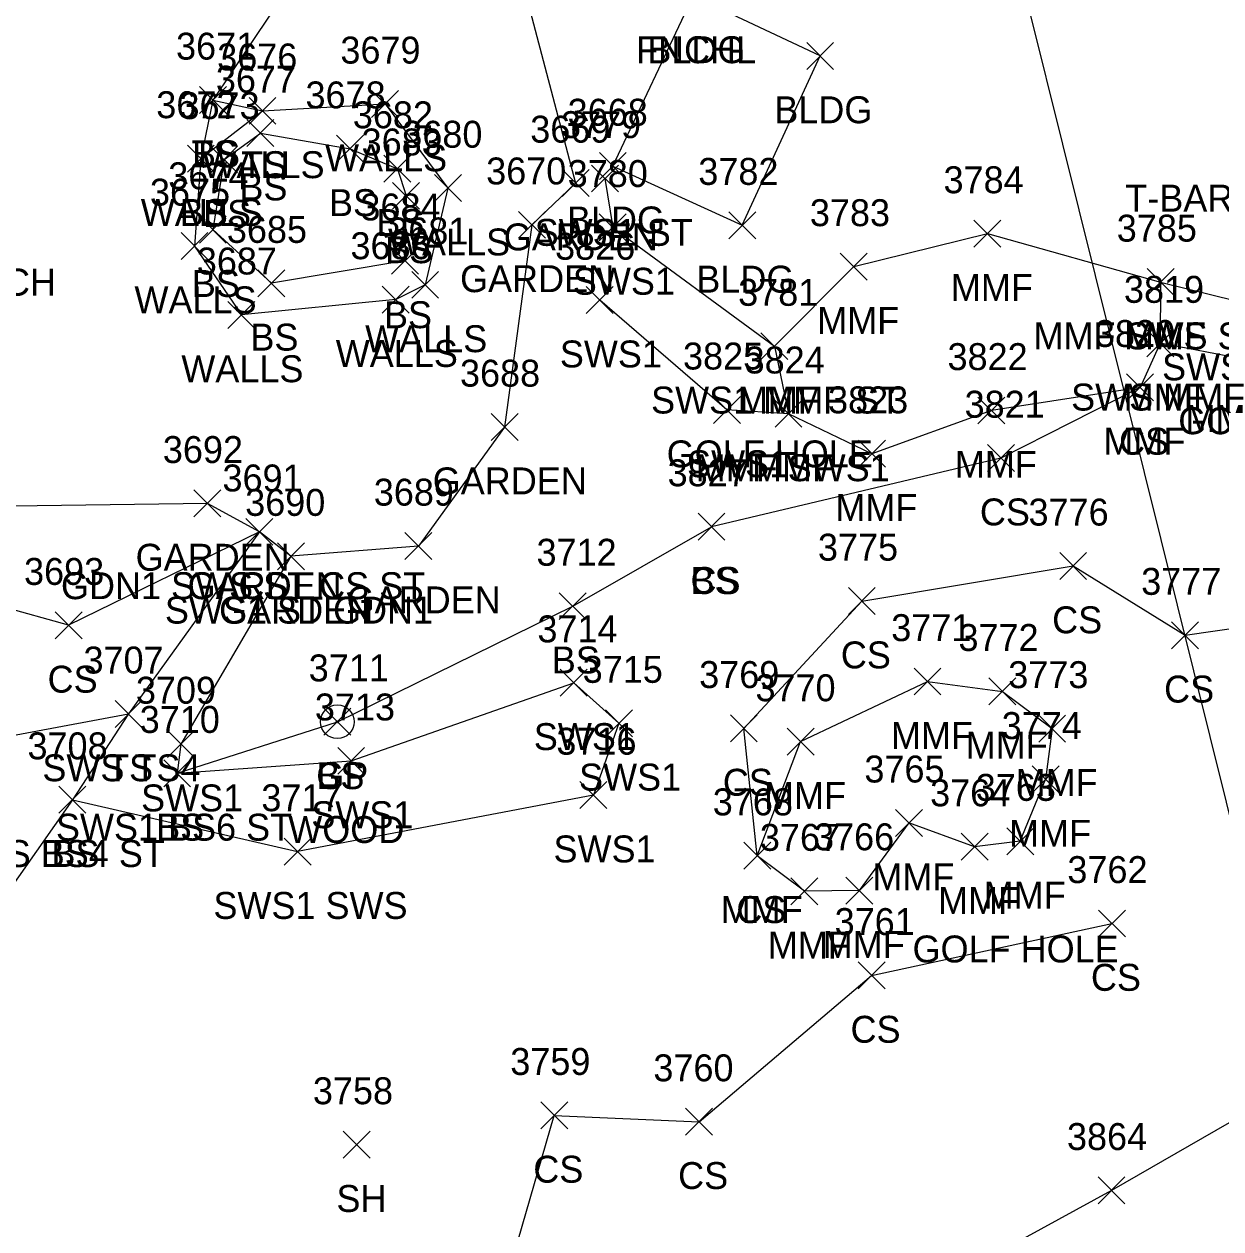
# Model space of a CAD drawing. Extents: x 49137 to 50946, y 9590 to 10709.
# Drawn here: x 49965.3 to 50054.1, y 10323.2 to 10412.7 of the extents above; entities that cross this region are included whole.
import ezdxf

# ---------------------------------------------------------------- set-up
doc = ezdxf.new("R2010")
doc.units = 0
for name, color, linetype in [('DCP', 7, 'Continuous'), ('L_A', 7, 'Continuous'), ('L_C', 7, 'Continuous'), ('L_I', 7, 'Continuous'), ('L_TIC', 7, 'Continuous'), ('LAPB', 7, 'Continuous'), ('LBC', 7, 'Continuous'), ('LDEFAULT', 7, 'Continuous'), ('LELB', 7, 'Continuous'), ('LWS', 7, 'Continuous'), ('R_A', 7, 'Continuous'), ('R_C', 7, 'Continuous'), ('R_I', 7, 'Continuous'), ('R_TIC', 7, 'Continuous'), ('RGP', 7, 'Continuous'), ('RSW', 7, 'Continuous')]:
    doc.layers.add(name, color=color, linetype=linetype)

msp = doc.modelspace()

# ---------------------------------------------------------------- linework, layer by layer
at = {"layer": 'DCP'}
msp.add_lwpolyline([(50149.417, 9973.365), (49988.848, 10619.092)], dxfattribs=at)
at = {"layer": 'L_TIC'}
for points in [[(50023.366, 10409.355), (50025.366, 10411.355)], [(50025.366, 10409.355), (50023.366, 10411.355)], [(49978.28, 10406.08), (49980.28, 10408.08)], [(49980.28, 10406.08), (49978.28, 10408.08)], [(49978.28, 10406.08), (49980.28, 10408.08)], [(49980.28, 10406.08), (49978.28, 10408.08)], [(49991.059, 10405.785), (49993.059, 10407.785)], [(49993.059, 10405.785), (49991.059, 10407.785)], [(49981.959, 10405.277), (49983.959, 10407.277)], [(49983.959, 10405.277), (49981.959, 10407.277)], [(49981.959, 10405.277), (49983.959, 10407.277)], [(49983.959, 10405.277), (49981.959, 10407.277)], [(49981.804, 10403.626), (49983.804, 10405.626)], [(49983.804, 10403.626), (49981.804, 10405.626)], [(49988.459, 10402.458), (49990.459, 10404.458)], [(49990.459, 10402.458), (49988.459, 10404.458)], [(49977.379, 10401.73), (49979.379, 10403.73)], [(49979.379, 10401.73), (49977.379, 10403.73)], [(49977.379, 10401.73), (49979.379, 10403.73)], [(49979.379, 10401.73), (49977.379, 10403.73)], [(49977.379, 10401.73), (49979.379, 10403.73)], [(49979.379, 10401.73), (49977.379, 10403.73)], [(49979.103, 10401.661), (49981.103, 10403.661)], [(49981.103, 10401.661), (49979.103, 10403.661)], [(49979.103, 10401.661), (49981.103, 10403.661)], [(49981.103, 10401.661), (49979.103, 10403.661)], [(50007.97, 10401.171), (50009.97, 10403.171)], [(50009.97, 10401.171), (50007.97, 10403.171)], [(50007.97, 10401.171), (50009.97, 10403.171)], [(50009.97, 10401.171), (50007.97, 10403.171)], [(49991.973, 10400.98), (49993.973, 10402.98)], [(49993.973, 10400.98), (49991.973, 10402.98)], [(49995.732, 10399.538), (49997.732, 10401.538)], [(49997.732, 10399.538), (49995.732, 10401.538)], [(50005.203, 10399.914), (50007.203, 10401.914)], [(50007.203, 10399.914), (50005.203, 10401.914)], [(49992.624, 10398.963), (49994.624, 10400.963)], [(49994.624, 10398.963), (49992.624, 10400.963)], [(50001.96, 10396.811), (50003.96, 10398.811)], [(50003.96, 10396.811), (50001.96, 10398.811)], [(50017.577, 10396.777), (50019.577, 10398.777)], [(50019.577, 10396.777), (50017.577, 10398.777)], [(49978.27, 10396.452), (49980.27, 10398.452)], [(49980.27, 10396.452), (49978.27, 10398.452)], [(50035.786, 10396.157), (50037.786, 10398.157)], [(50037.786, 10396.157), (50035.786, 10398.157)], [(49976.91, 10395.237), (49978.91, 10397.237)], [(49978.91, 10395.237), (49976.91, 10397.237)], [(49992.535, 10394.136), (49994.535, 10396.136)], [(49994.535, 10394.136), (49992.535, 10396.136)], [(50025.86, 10393.712), (50027.86, 10395.712)], [(50027.86, 10393.712), (50025.86, 10395.712)], [(49982.62, 10392.47), (49984.62, 10394.47)], [(49984.62, 10392.47), (49982.62, 10394.47)], [(49982.62, 10392.47), (49984.62, 10394.47)], [(49984.62, 10392.47), (49982.62, 10394.47)], [(49994.036, 10392.354), (49996.036, 10394.354)], [(49996.036, 10392.354), (49994.036, 10394.354)], [(50048.646, 10392.563), (50050.646, 10394.563)], [(50050.646, 10392.563), (50048.646, 10394.563)], [(49991.854, 10391.259), (49993.854, 10393.259)], [(49993.854, 10391.259), (49991.854, 10393.259)], [(49980.389, 10390.123), (49982.389, 10392.123)], [(49982.389, 10390.123), (49980.389, 10392.123)], [(49980.389, 10390.123), (49982.389, 10392.123)], [(49982.389, 10390.123), (49980.389, 10392.123)], [(50019.968, 10387.798), (50021.968, 10389.798)], [(50021.968, 10387.798), (50019.968, 10389.798)], [(50048.621, 10388.018), (50050.621, 10390.018)], [(50050.621, 10388.018), (50048.621, 10390.018)], [(50047.112, 10384.74), (50049.112, 10386.74)], [(50049.112, 10384.74), (50047.112, 10386.74)], [(50047.112, 10384.74), (50049.112, 10386.74)], [(50049.112, 10384.74), (50047.112, 10386.74)], [(50021.015, 10382.772), (50023.015, 10384.772)], [(50023.015, 10382.772), (50021.015, 10384.772)], [(50036.08, 10383.022), (50038.08, 10385.022)], [(50038.08, 10383.022), (50036.08, 10385.022)], [(49999.93, 10381.794), (50001.93, 10383.794)], [(50001.93, 10381.794), (49999.93, 10383.794)], [(50027.208, 10379.812), (50029.208, 10381.812)], [(50029.208, 10379.812), (50027.208, 10381.812)], [(50036.783, 10379.488), (50038.783, 10381.488)], [(50038.783, 10379.488), (50036.783, 10381.488)], [(49977.869, 10376.122), (49979.869, 10378.122)], [(49979.869, 10376.122), (49977.869, 10378.122)], [(50015.297, 10374.395), (50017.297, 10376.395)], [(50017.297, 10374.395), (50015.297, 10376.395)], [(50015.297, 10374.395), (50017.297, 10376.395)], [(50017.297, 10374.395), (50015.297, 10376.395)], [(49981.728, 10374.011), (49983.728, 10376.011)], [(49983.728, 10374.011), (49981.728, 10376.011)], [(49981.728, 10374.011), (49983.728, 10376.011)], [(49983.728, 10374.011), (49981.728, 10376.011)], [(49993.536, 10372.957), (49995.536, 10374.957)], [(49995.536, 10372.957), (49993.536, 10374.957)], [(49984.067, 10372.198), (49986.067, 10374.198)], [(49986.067, 10372.198), (49984.067, 10374.198)], [(50042.148, 10371.476), (50044.148, 10373.476)], [(50044.148, 10371.476), (50042.148, 10373.476)], [(50004.996, 10368.493), (50006.996, 10370.493)], [(50006.996, 10368.493), (50004.996, 10370.493)], [(50026.458, 10368.871), (50028.458, 10370.871)], [(50028.458, 10368.871), (50026.458, 10370.871)], [(49967.562, 10367.069), (49969.562, 10369.069)], [(49969.562, 10367.069), (49967.562, 10369.069)], [(50050.46, 10366.333), (50052.46, 10368.333)], [(50052.46, 10366.333), (50050.46, 10368.333)], [(50031.333, 10362.895), (50033.333, 10364.895)], [(50033.333, 10362.895), (50031.333, 10364.895)], [(50036.893, 10362.163), (50038.893, 10364.163)], [(50038.893, 10362.163), (50036.893, 10364.163)], [(49972.009, 10360.489), (49974.009, 10362.489)], [(49974.009, 10360.489), (49972.009, 10362.489)], [(49987.517, 10359.904), (49989.517, 10361.904)], [(49989.517, 10359.904), (49987.517, 10361.904)], [(50017.697, 10359.413), (50019.697, 10361.413)], [(50019.697, 10359.413), (50017.697, 10361.413)], [(50040.591, 10359.403), (50042.591, 10361.403)], [(50042.591, 10359.403), (50040.591, 10361.403)], [(50021.908, 10358.429), (50023.908, 10360.429)], [(50023.908, 10358.429), (50021.908, 10360.429)], [(49975.622, 10356.077), (49977.622, 10358.077)], [(49977.622, 10356.077), (49975.622, 10358.077)], [(50040.104, 10355.622), (50042.104, 10357.622)], [(50042.104, 10355.622), (50040.104, 10357.622)], [(50040.104, 10355.622), (50042.104, 10357.622)], [(50042.104, 10355.622), (50040.104, 10357.622)], [(49967.847, 10354.118), (49969.847, 10356.118)], [(49969.847, 10354.118), (49967.847, 10356.118)], [(50029.956, 10352.395), (50031.956, 10354.395)], [(50031.956, 10352.395), (50029.956, 10354.395)], [(50034.836, 10350.628), (50036.836, 10352.628)], [(50036.836, 10350.628), (50034.836, 10352.628)], [(50038.223, 10351.032), (50040.223, 10353.032)], [(50040.223, 10351.032), (50038.223, 10353.032)], [(50038.223, 10351.032), (50040.223, 10353.032)], [(50040.223, 10351.032), (50038.223, 10353.032)], [(50018.697, 10349.956), (50020.697, 10351.956)], [(50020.697, 10349.956), (50018.697, 10351.956)], [(50018.697, 10349.956), (50020.697, 10351.956)], [(50020.697, 10349.956), (50018.697, 10351.956)], [(50022.196, 10347.321), (50024.196, 10349.321)], [(50024.196, 10347.321), (50022.196, 10349.321)], [(50026.271, 10347.363), (50028.271, 10349.363)], [(50028.271, 10347.363), (50026.271, 10349.363)], [(50045.027, 10344.926), (50047.027, 10346.926)], [(50047.027, 10344.926), (50045.027, 10346.926)], [(50027.179, 10341.067), (50029.179, 10343.067)], [(50029.179, 10341.067), (50027.179, 10343.067)], [(50003.625, 10330.677), (50005.625, 10332.677)], [(50005.625, 10330.677), (50003.625, 10332.677)], [(50014.376, 10330.206), (50016.376, 10332.206)], [(50016.376, 10330.206), (50014.376, 10332.206)], [(49988.961, 10328.503), (49990.961, 10330.503)], [(49990.961, 10328.503), (49988.961, 10330.503)], [(50044.996, 10325.102), (50046.996, 10327.102)], [(50046.996, 10325.102), (50044.996, 10327.102)]]:
    msp.add_lwpolyline(points, dxfattribs=at)
at = {"layer": 'LAPB'}
msp.add_lwpolyline([(49952.358, 10434.146), (49968.592, 10432.435), (49977.813, 10428.307), (49990.651, 10424.08), (50000.797, 10421.39), (50006.203, 10400.914), (50002.96, 10397.811), (50000.93, 10382.794), (49994.536, 10373.957), (49985.067, 10373.198), (49982.728, 10375.011), (49978.869, 10377.122), (49955.361, 10376.803), (49948.643, 10373.628)], dxfattribs=at)
at = {"layer": 'LBC'}
for points in [[(50008.97, 10402.171), (50018.577, 10397.777), (50024.366, 10410.355), (50014.946, 10414.815)], [(50008.97, 10402.171), (50014.946, 10414.815)]]:
    msp.add_lwpolyline(points, dxfattribs=at)
at = {"layer": 'LDEFAULT'}
for points in [[(50020.968, 10388.798), (50026.86, 10394.712), (50036.786, 10397.157), (50049.646, 10393.563), (50049.621, 10389.018), (50048.112, 10385.74), (50037.08, 10384.022), (50028.208, 10380.812), (50022.015, 10383.772)], [(50039.223, 10352.032), (50035.836, 10351.628), (50030.956, 10353.395), (50027.271, 10348.363), (50023.196, 10348.321), (50019.697, 10350.956), (50022.908, 10359.429), (50032.333, 10363.895), (50037.893, 10363.163), (50041.591, 10360.403), (50041.104, 10356.622)], [(50039.223, 10352.032), (50041.104, 10356.622)]]:
    msp.add_lwpolyline(points, dxfattribs=at)
at = {"layer": 'LELB'}
for points in [[(49990.651, 10424.08), (49979.28, 10407.08), (49978.379, 10402.73)], [(49979.28, 10407.08), (49982.959, 10406.277)], [(49980.103, 10402.661), (49982.804, 10404.626), (49989.459, 10403.458), (49992.973, 10401.98), (49993.624, 10399.963), (49993.535, 10395.136), (49983.62, 10393.47)], [(49980.103, 10402.661), (49979.27, 10397.452), (49983.62, 10393.47)], [(50048.112, 10385.74), (50037.783, 10380.488), (50016.297, 10375.395)], [(50019.697, 10350.956), (50018.697, 10360.413), (50027.458, 10369.871), (50043.148, 10372.476), (50051.46, 10367.333), (50060.907, 10368.69), (50071.028, 10377.965)], [(49982.728, 10375.011), (49968.562, 10368.069), (49948.643, 10373.628)], [(49976.622, 10357.077), (49988.517, 10360.904), (50005.996, 10369.493), (50016.297, 10375.395)], [(49926.539, 10346.599), (49938.324, 10352.703), (49953.777, 10357.903), (49973.009, 10361.489)], [(49968.847, 10355.118), (49955.47, 10336.036), (49948.518, 10322.541), (49945.706, 10295.254), (49955.228, 10276.315), (49969.259, 10262.531), (49976.787, 10237.905)], [(49969.259, 10262.531), (49980.294, 10281.069), (49996.572, 10303.842), (50004.625, 10331.677), (50015.376, 10331.206), (50028.179, 10342.067), (50046.027, 10345.926)], [(50066.256, 10337.749), (50045.996, 10326.102), (50031.571, 10318.205), (50024.186, 10311.328), (50008.365, 10283.785), (50010.84, 10269.9), (50019.682, 10261.76), (50041.865, 10254.082), (50068.201, 10243.093)]]:
    msp.add_lwpolyline(points, dxfattribs=at)
at = {"layer": 'LWS'}
for points in [[(49978.379, 10402.73), (49982.959, 10406.277), (49992.059, 10406.785), (49996.732, 10400.538), (49995.036, 10393.354), (49992.854, 10392.259), (49981.389, 10391.123)], [(49978.379, 10402.73), (49977.91, 10396.237), (49981.389, 10391.123)]]:
    msp.add_lwpolyline(points, dxfattribs=at)
at = {"layer": 'R_TIC'}
for points in [[(50007.387, 10400.251), (50009.387, 10402.251)], [(50009.387, 10400.251), (50007.387, 10402.251)], [(50007.963, 10396.62), (50009.963, 10398.62)], [(50009.963, 10396.62), (50007.963, 10398.62)], [(50048.646, 10392.563), (50050.646, 10394.563)], [(50050.646, 10392.563), (50048.646, 10394.563)], [(50006.998, 10391.22), (50008.998, 10393.22)], [(50008.998, 10391.22), (50006.998, 10393.22)], [(50019.968, 10387.798), (50021.968, 10389.798)], [(50021.968, 10387.798), (50019.968, 10389.798)], [(50048.621, 10388.018), (50050.621, 10390.018)], [(50050.621, 10388.018), (50048.621, 10390.018)], [(50016.443, 10383.066), (50018.443, 10385.066)], [(50018.443, 10383.066), (50016.443, 10385.066)], [(50021.015, 10382.772), (50023.015, 10384.772)], [(50023.015, 10382.772), (50021.015, 10384.772)], [(49981.728, 10374.011), (49983.728, 10376.011)], [(49983.728, 10374.011), (49981.728, 10376.011)], [(49984.067, 10372.198), (49986.067, 10374.198)], [(49986.067, 10372.198), (49984.067, 10374.198)], [(50005.065, 10362.803), (50007.065, 10364.803)], [(50007.065, 10362.803), (50005.065, 10364.803)], [(49972.009, 10360.489), (49974.009, 10362.489)], [(49974.009, 10360.489), (49972.009, 10362.489)], [(50008.426, 10359.798), (50010.426, 10361.798)], [(50010.426, 10359.798), (50008.426, 10361.798)], [(49975.906, 10358.249), (49977.906, 10360.249)], [(49977.906, 10358.249), (49975.906, 10360.249)], [(49988.541, 10357.004), (49990.541, 10359.004)], [(49990.541, 10357.004), (49988.541, 10359.004)], [(49975.622, 10356.077), (49977.622, 10358.077)], [(49977.622, 10356.077), (49975.622, 10358.077)], [(49967.847, 10354.118), (49969.847, 10356.118)], [(49969.847, 10354.118), (49967.847, 10356.118)], [(50006.526, 10354.461), (50008.526, 10356.461)], [(50008.526, 10354.461), (50006.526, 10356.461)], [(49984.568, 10350.265), (49986.568, 10352.265)], [(49986.568, 10350.265), (49984.568, 10352.265)], [(49984.568, 10350.265), (49986.568, 10352.265)], [(49986.568, 10350.265), (49984.568, 10352.265)]]:
    msp.add_lwpolyline(points, dxfattribs=at)
at = {"layer": 'RGP'}
msp.add_line((49988.517, 10360.904), (49988.517, 10360.904), dxfattribs=at)
for radius in [1.25, 0.0833]:
    msp.add_circle((49988.517, 10360.904), radius, dxfattribs=at)
at = {"layer": 'RSW'}
for points in [[(50008.387, 10401.251), (50008.963, 10397.62), (50020.968, 10388.798), (50022.015, 10383.772), (50017.443, 10384.066), (50007.998, 10392.22)], [(50049.646, 10393.563), (50058.954, 10391.261), (50057.822, 10387.436), (50049.621, 10389.018)], [(49982.728, 10375.011), (49973.009, 10361.489), (49968.847, 10355.118), (49985.568, 10351.265)], [(49985.067, 10373.198), (49976.906, 10359.249), (49976.622, 10357.077), (49989.541, 10358.004), (50006.065, 10363.803), (50009.426, 10360.798), (50007.526, 10355.461), (49985.568, 10351.265)]]:
    msp.add_lwpolyline(points, dxfattribs=at)

# ---------------------------------------------------------------- texts
at = {"layer": 'L_A'}
for s, p in [('FNCHL', (50010.694, 10409.815)), ('BLDG', (50011.536, 10409.815)), ('BLDG', (50011.536, 10409.815)), ('BLDG', (50020.957, 10405.355)), ('TS', (49977.689, 10402.08)), ('BS', (49977.721, 10402.08)), ('WALLS', (49978.502, 10401.277)), ('TS', (49981.368, 10401.277)), ('WALLS', (49987.602, 10401.785)), ('BS', (49981.245, 10399.626)), ('BS', (49987.9, 10398.458)), ('WALLS', (49973.922, 10397.73)), ('WALLS', (49973.922, 10397.73)), ('BS', (49976.82, 10397.73)), ('BS', (49978.544, 10397.661)), ('BS', (49978.544, 10397.661)), ('BS', (49991.413, 10396.98)), ('BLDG', (50005.56, 10397.171)), ('BLDG', (50005.56, 10397.171)), ('GARDEN', (50000.872, 10395.914)), ('BS', (49992.065, 10394.963)), ('WALLS', (49992.275, 10395.538)), ('BS', (49977.711, 10392.452)), ('GARDEN', (49997.629, 10392.811)), ('BLDG', (50015.168, 10392.777)), ('MMF', (50034.07, 10392.157)), ('WALLS', (49973.453, 10391.237)), ('BS', (49991.976, 10390.136)), ('MMF', (50024.144, 10389.712)), ('BS', (49982.061, 10388.47)), ('BS', (49982.061, 10388.47)), ('WALLS', (49990.58, 10388.354)), ('MMF', (50046.93, 10388.563)), ('WALLS', (49988.398, 10387.259)), ('WALLS', (49976.933, 10386.123)), ('WALLS', (49976.933, 10386.123)), ('MMF', (50018.251, 10383.798)), ('MMF', (50046.905, 10384.018)), ('MMF', (50045.395, 10380.74)), ('CS', (50046.553, 10380.74)), ('MMF', (50034.364, 10379.022)), ('MMF', (50019.299, 10378.772)), ('GARDEN', (49995.599, 10377.794)), ('MMF', (50025.492, 10375.812)), ('CS', (50036.224, 10375.488)), ('GARDEN', (49973.538, 10372.122)), ('GARDEN', (49977.397, 10370.011)), ('CS', (49981.169, 10370.011)), ('CS', (50014.738, 10370.395)), ('BS', (50014.738, 10370.395)), ('GARDEN', (49989.206, 10368.957)), ('GARDEN', (49979.737, 10368.198)), ('CS', (50041.589, 10367.476)), ('BS', (50004.437, 10364.493)), ('CS', (50025.899, 10364.871)), ('CS', (49967.003, 10363.069)), ('CS', (50049.901, 10362.333)), ('MMF', (50029.617, 10358.895)), ('MMF', (50035.176, 10358.163)), ('TS', (49971.418, 10356.489)), ('BS', (49986.958, 10355.904)), ('CS', (50017.138, 10355.413)), ('MMF', (50038.875, 10355.403)), ('MMF', (50020.192, 10354.429)), ('BS', (49975.063, 10352.077)), ('MMF', (50038.387, 10351.622)), ('MMF', (50038.387, 10351.622)), ('BS', (49967.288, 10350.118)), ('MMF', (50028.239, 10348.395)), ('MMF', (50033.12, 10346.628)), ('MMF', (50036.507, 10347.032)), ('MMF', (50036.507, 10347.032)), ('MMF', (50016.98, 10345.956)), ('CS', (50018.138, 10345.956)), ('MMF', (50020.48, 10343.321)), ('MMF', (50024.555, 10343.363)), ('CS', (50044.468, 10340.926)), ('CS', (50026.62, 10337.067)), ('CS', (50003.066, 10326.677)), ('CS', (50013.817, 10326.206)), ('SH', (49988.45, 10324.503))]:
    msp.add_text(s, height=2, dxfattribs=at).set_placement(p)
at = {"layer": 'L_C'}
for s, p in [('T-BAR LIFT LINE', (50047.02, 10398.792)), ('T-BAR LIFT LINE', (50047.02, 10398.792)), ('3-M.YBIRCH', (49952.175, 10392.554)), ('GOLF HOLE', (50031.223, 10343.032)), ('GOLF HOLE', (50031.223, 10343.032))]:
    msp.add_text(s, height=2, dxfattribs=at).set_placement(p)
at = {"layer": 'L_I'}
for s, p in [('3671', (49976.54, 10410.08)), ('3671', (49976.54, 10410.08)), ('3676', (49979.596, 10409.277)), ('3676', (49979.596, 10409.277)), ('3679', (49988.744, 10409.785)), ('3677', (49979.497, 10407.626)), ('3672', (49975.072, 10405.73)), ('3672', (49975.072, 10405.73)), ('3672', (49975.072, 10405.73)), ('3673', (49976.796, 10405.661)), ('3673', (49976.796, 10405.661)), ('3678', (49986.152, 10406.458)), ('3682', (49989.665, 10404.98)), ('3668', (50005.615, 10405.171)), ('3668', (50005.615, 10405.171)), ('3669', (50002.84, 10403.914)), ('3683', (49990.317, 10402.963)), ('3680', (49993.338, 10403.538)), ('3674', (49975.963, 10400.452)), ('3670', (49999.566, 10400.811)), ('3782', (50015.318, 10400.777)), ('3784', (50033.526, 10400.157)), ('3675', (49974.603, 10399.237)), ('3684', (49990.228, 10398.136)), ('3783', (50023.601, 10397.712)), ('3685', (49980.313, 10396.47)), ('3685', (49980.313, 10396.47)), ('3681', (49992.296, 10396.354)), ('3785', (50046.386, 10396.563)), ('3686', (49989.492, 10395.259)), ('3687', (49978.082, 10394.123)), ('3687', (49978.082, 10394.123)), ('3781', (50018.275, 10391.798)), ('3819', (50046.92, 10392.018)), ('3820', (50044.765, 10388.74)), ('3820', (50044.765, 10388.74)), ('3822', (50033.82, 10387.022)), ('3824', (50018.755, 10386.772)), ('3688', (49997.623, 10385.794)), ('3823', (50024.949, 10383.812)), ('3821', (50035.09, 10383.488)), ('3692', (49975.561, 10380.122)), ('3691', (49979.988, 10378.011)), ('3691', (49979.988, 10378.011)), ('3827', (50013.037, 10378.395)), ('3827', (50013.037, 10378.395)), ('3690', (49981.674, 10376.198)), ('3689', (49991.222, 10376.957)), ('3776', (50039.834, 10375.476)), ('3712', (50003.304, 10372.493)), ('3775', (50024.199, 10372.871)), ('3693', (49965.255, 10371.069)), ('3777', (50048.2, 10370.333)), ('3771', (50029.641, 10366.895)), ('3772', (50034.633, 10366.163)), ('3707', (49969.67, 10364.489)), ('3711', (49986.391, 10363.904)), ('3769', (50015.382, 10363.413)), ('3773', (50038.332, 10363.403)), ('3770', (50019.562, 10362.429)), ('3710', (49973.842, 10360.077)), ('3774', (50037.844, 10359.622)), ('3774', (50037.844, 10359.622)), ('3708', (49965.509, 10358.118)), ('3765', (50027.649, 10356.395)), ('3764', (50032.529, 10354.628)), ('3763', (50035.916, 10355.032)), ('3763', (50035.916, 10355.032)), ('3768', (50016.39, 10353.956)), ('3768', (50016.39, 10353.956)), ('3767', (50019.889, 10351.321)), ('3766', (50023.909, 10351.363)), ('3762', (50042.72, 10348.926)), ('3761', (50025.439, 10345.067)), ('3759', (50001.357, 10334.677)), ('3760', (50011.983, 10334.206)), ('3758', (49986.702, 10332.503)), ('3864', (50042.689, 10329.102))]:
    msp.add_text(s, height=2, dxfattribs=at).set_placement(p)
at = {"layer": 'R_A'}
for s, p in [('SWS1 ST', (50003.167, 10396.251)), ('SWS1', (50006.002, 10392.62)), ('MMF SWS ST', (50040.205, 10388.563)), ('SWS1', (50005.037, 10387.22)), ('SWS MMF1 ST', (50049.75, 10386.261)), ('SWS1 MMF ST', (50011.811, 10383.798)), ('SWS MMF', (50042.999, 10384.018)), ('MMF1 SWS', (50051.491, 10382.436)), ('SWS1', (50014.482, 10379.066)), ('MMF SWS1', (50015.118, 10378.772)), ('GDN1 SWS ST CS ST', (49967.996, 10370.011)), ('SWS1 ST GDN1', (49975.713, 10368.198)), ('SWS1', (50003.104, 10358.803)), ('SWS TS4', (49966.615, 10356.489)), ('GP', (49986.95, 10355.904)), ('SWS1', (50006.465, 10355.798)), ('SWS1', (49973.945, 10354.249)), ('SWS1', (49986.581, 10353.004)), ('SWS1 BS6 ST', (49967.622, 10352.077)), ('SWS BS4 ST', (49959.659, 10350.118)), ('SWS1', (50004.566, 10350.461)), ('SWS1 SWS', (49979.316, 10346.265)), ('SWS1 SWS', (49979.316, 10346.265))]:
    msp.add_text(s, height=2, dxfattribs=at).set_placement(p)
at = {"layer": 'R_C'}
for s, p in [('GOLF HOLE', (50050.954, 10382.261)), ('GOLF HOLE', (50012.968, 10379.798)), ('WOOD', (49984.872, 10351.904))]:
    msp.add_text(s, height=2, dxfattribs=at).set_placement(p)
at = {"layer": 'R_I'}
for s, p in [('3779', (50005.119, 10404.251)), ('3780', (50005.617, 10400.62)), ('3785', (50046.386, 10396.563)), ('3826', (50004.683, 10395.22)), ('3781', (50018.275, 10391.798)), ('3819', (50046.92, 10392.018)), ('3825', (50014.183, 10387.066)), ('3824', (50018.755, 10386.772)), ('3691', (49979.988, 10378.011)), ('3690', (49981.674, 10376.198)), ('3714', (50003.372, 10366.803)), ('3707', (49969.67, 10364.489)), ('3711', (49986.391, 10363.904)), ('3715', (50006.733, 10363.798)), ('3709', (49973.56, 10362.249)), ('3713', (49986.849, 10361.004)), ('3710', (49973.842, 10360.077)), ('3716', (50004.779, 10358.461)), ('3708', (49965.509, 10358.118)), ('3717', (49982.875, 10354.265)), ('3717', (49982.875, 10354.265))]:
    msp.add_text(s, height=2, dxfattribs=at).set_placement(p)

doc.saveas('drawing.dxf')
